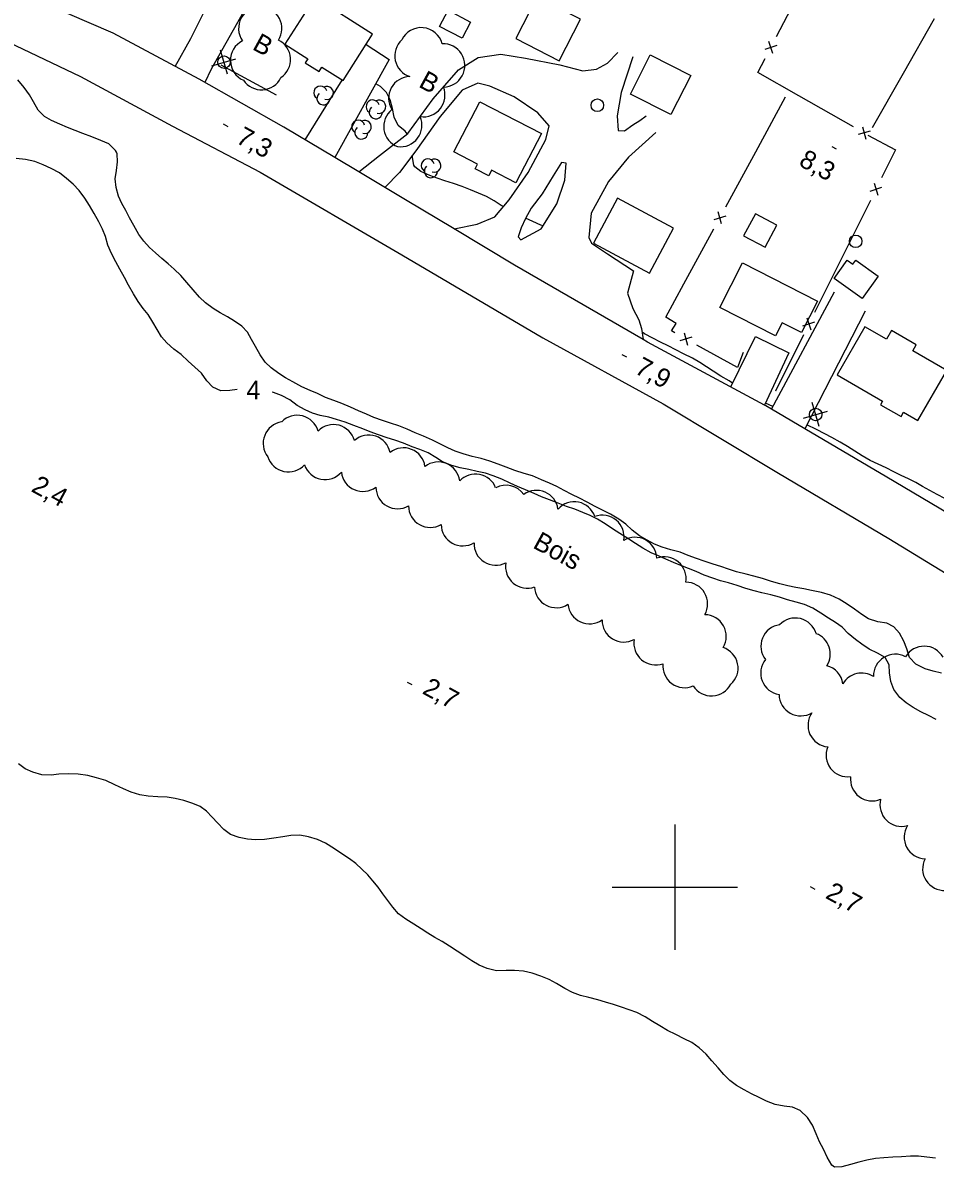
# Model space of a CAD drawing. Extents: x 219136 to 222520, y 5421589 to 5424530.
# Drawn here: x 220895.9 to 221041.6, y 5422955.3 to 5423137.9 of the extents above; entities that cross this region are included whole.
import ezdxf

# ---------------------------------------------------------------- set-up
doc = ezdxf.new("R2010")
doc.units = 0
for name, color, linetype in [('Level 19', 7, 'Continuous'), ('Level 2', 7, 'Continuous'), ('Level 21', 7, 'Continuous'), ('Level 3', 7, 'Continuous'), ('Level 31', 7, 'Continuous'), ('Level 36', 7, 'Continuous'), ('Level 37', 7, 'Continuous'), ('Level 4', 7, 'Continuous'), ('Level 44', 7, 'Continuous'), ('Level 61', 7, 'Continuous')]:
    doc.layers.add(name, color=color, linetype=linetype)

msp = doc.modelspace()

# ---------------------------------------------------------------- linework, layer by layer
at = {"layer": 'Level 19'}
for points in [[(220929.6, 5423148.91), (220934.65, 5423145.93), (220925.97, 5423130.51), (220924.96, 5423128.39)], [(220920.26, 5423130.93), (220922.77, 5423135.39), (220925.45, 5423140.81)], [(220950.72, 5423134.47), (220954.42, 5423132.05), (220945.73, 5423116.39)], [(220949.57, 5423114.1), (220952.89, 5423116.75), (220957.38, 5423120.25), (220961.41, 5423125.76), (220965.45, 5423130.42), (220968.62, 5423132.38), (220972.22, 5423132.91), (220976.18, 5423132.29), (220981.66, 5423131.19), (220985.35, 5423130.24), (220987.53, 5423130.51), (220989.26, 5423131.46), (220990.89, 5423133.17)], [(220993.31, 5423132.5), (220991.42, 5423126.77), (220990.8, 5423123.04), (220990.94, 5423120.72), (220991.99, 5423120.68), (220993.29, 5423121.62), (220994.43, 5423122.33), (220995.41, 5423123.07)], [(220940.99, 5423119.21), (220946.93, 5423128.78)], [(220964.79, 5423105.01), (220968.48, 5423105.8), (220971.27, 5423106.92), (220973.54, 5423109.66), (220976.59, 5423114.01), (220979.41, 5423119.29), (220979.95, 5423121.46), (220978.15, 5423123.52), (220974.34, 5423126.1), (220970.46, 5423127.8), (220968.57, 5423128.28), (220966.08, 5423127.15), (220962.54, 5423122.94), (220958.65, 5423117.46), (220956.07, 5423114.04), (220953.7, 5423111.63)], [(220996.98, 5423120.4), (220992.62, 5423116.45), (220989.41, 5423112.56), (220986.68, 5423107.53), (220986.27, 5423103.66), (220986.71, 5423102.74), (220989.25, 5423101.03), (220993.39, 5423098.32), (220992.43, 5423094.78), (220993.32, 5423092.31), (220994.24, 5423090.52), (220994.71, 5423089.15), (220994.96, 5423087.38)], [(220975.45, 5423103.27), (220978.68, 5423105.04), (220981.18, 5423109), (220982.45, 5423112.79), (220982.69, 5423115.5), (220981.94, 5423115.64), (220980.59, 5423113.47), (220978.85, 5423110.64), (220977.07, 5423108.33), (220976.15, 5423106.69), (220975.47, 5423105.17), (220975.01, 5423103.76), (220975.45, 5423103.27)], [(221015.43, 5423076.25), (221025.5, 5423095)], [(221030.41, 5423091.87), (221020.74, 5423073.12)], [(221008.93, 5423079.8), (221012.87, 5423087.85), (221018.21, 5423085.23), (221014.35, 5423076.87)]]:
    msp.add_lwpolyline(points, dxfattribs=at)
at = {"layer": 'Level 2'}
for points in [[(220900.48, 5423122.34), (220899.38, 5423122.94), (220898.37, 5423123.96), (220897.61, 5423125.3), (220897.01, 5423126.4), (220896.13, 5423127.61), (220895.15, 5423128.81)], [(220957.29, 5423120.18), (220956.97, 5423120.6), (220955.86, 5423121.52), (220955.21, 5423122.84), (220954.93, 5423124.21), (220954.55, 5423125.63), (220953.97, 5423126.79), (220953.01, 5423127.72), (220952.26, 5423128.16)], [(220963.77, 5423070.06), (220962.5, 5423070.72), (220961.34, 5423071.31), (220959.87, 5423071.94), (220958.55, 5423072.49), (220957.29, 5423073.06), (220955.94, 5423073.6), (220954.62, 5423074.04), (220953.34, 5423074.43), (220951.94, 5423074.93), (220950.77, 5423075.43), (220949.52, 5423076.01), (220948.22, 5423076.58), (220946.84, 5423077.15), (220945.6, 5423077.61), (220944.23, 5423078.14), (220942.99, 5423078.73), (220941.77, 5423079.23), (220940.48, 5423079.82), (220939.03, 5423080.59), (220937.88, 5423081.25), (220936.82, 5423081.92), (220935.59, 5423082.85), (220934.63, 5423083.77), (220933.79, 5423084.93), (220933.06, 5423086.24), (220932.45, 5423087.36), (220931.78, 5423088.54), (220930.87, 5423089.51), (220929.73, 5423090.31), (220928.59, 5423091.01), (220927.41, 5423091.63), (220926.3, 5423092.33), (220925.1, 5423093.23), (220924.14, 5423094.13), (220923.11, 5423095.31), (220922.11, 5423096.47), (220921.13, 5423097.59), (220920.08, 5423098.58), (220919.15, 5423099.43), (220918.1, 5423100.32), (220917.11, 5423101.18), (220916.17, 5423102.03), (220915.23, 5423103.06), (220914.43, 5423104.15), (220913.66, 5423105.55), (220912.96, 5423106.81), (220912.35, 5423107.93), (220911.74, 5423109.06), (220911.21, 5423110.24), (220910.85, 5423111.64), (220910.67, 5423113), (220910.86, 5423114.32), (220911.03, 5423115.71), (220910.97, 5423117), (220910.89, 5423117.26), (220910.73, 5423117.51), (220909.65, 5423118.59), (220908.36, 5423119.15), (220906.94, 5423119.7), (220905.5, 5423120.26), (220904.26, 5423120.72), (220903.04, 5423121.2), (220901.84, 5423121.74), (220900.48, 5423122.34)], [(220917.35, 5423088.94), (220916.68, 5423090.15), (220915.95, 5423091.36), (220915.16, 5423092.33), (220914.34, 5423093.42), (220913.57, 5423094.65), (220912.82, 5423096.02), (220912.13, 5423097.29), (220911.43, 5423098.57), (220910.79, 5423099.77), (220910.07, 5423101.12), (220909.52, 5423102.45), (220909.11, 5423103.78), (220908.65, 5423104.96), (220908.05, 5423106.14), (220907.33, 5423107.46), (220906.57, 5423108.74), (220905.84, 5423109.92), (220904.93, 5423111.15), (220903.95, 5423112.15), (220902.9, 5423113.06), (220901.78, 5423113.94), (220900.47, 5423114.65), (220899.17, 5423115.26), (220897.82, 5423115.79), (220896.35, 5423116.11), (220894.88, 5423116.24)], [(220972.65, 5423108.59), (220972.3, 5423108.78), (220971.15, 5423109.48), (220969.96, 5423110.18), (220968.65, 5423110.74), (220967.38, 5423111.26), (220966.06, 5423111.8), (220964.66, 5423112.27), (220963.29, 5423112.69), (220962.09, 5423113.11), (220960.88, 5423113.55), (220959.44, 5423114.17), (220958.48, 5423114.9), (220958.33, 5423115.17), (220958.1, 5423116.72)], [(220978.98, 5423105.52), (220978.61, 5423105.64), (220977.32, 5423106.19), (220976.18, 5423106.75)], [(220930.14, 5423079.37), (220928.99, 5423079.25), (220927.54, 5423079.19), (220926.25, 5423079.77), (220925.31, 5423080.77), (220924.46, 5423081.98), (220923.39, 5423082.93), (220922.32, 5423083.91), (220921.18, 5423084.95), (220920.03, 5423085.83), (220918.91, 5423086.85), (220918.05, 5423087.8), (220917.35, 5423088.94)], [(221005.07, 5423083.03), (221004.02, 5423083.71), (221002.83, 5423084.38), (221001.4, 5423085.07), (221000.15, 5423085.71), (220998.94, 5423086.38), (220997.73, 5423086.97), (220996.49, 5423087.57), (220995.18, 5423088.28), (220994.8, 5423088.53)], [(221009.23, 5423080.42), (221008.69, 5423080.75), (221007.38, 5423081.52), (221006.14, 5423082.33), (221005.07, 5423083.03)], [(220997.38, 5423052.83), (220996.21, 5423053.34), (220994.89, 5423054.07), (220993.74, 5423054.81), (220992.49, 5423055.6), (220991.22, 5423056.43), (220990.06, 5423057.17), (220988.88, 5423057.94), (220987.67, 5423058.69), (220986.49, 5423059.28), (220985.3, 5423059.78), (220984.05, 5423060.27), (220982.72, 5423060.74), (220981.38, 5423061.26), (220979.99, 5423061.78), (220978.74, 5423062.27), (220977.53, 5423062.81), (220976.15, 5423063.37), (220974.89, 5423063.9), (220973.73, 5423064.47), (220972.4, 5423065.07), (220971.02, 5423065.63), (220969.79, 5423066.03), (220968.47, 5423066.32), (220967.11, 5423066.62), (220965.76, 5423066.9), (220964.39, 5423067.25), (220962.93, 5423067.87), (220961.85, 5423068.55), (220960.62, 5423069.29), (220959.32, 5423069.82), (220958.07, 5423070.26), (220956.72, 5423070.82), (220955.31, 5423071.32), (220954.11, 5423071.67), (220952.7, 5423072.15), (220951.4, 5423072.62), (220950.19, 5423073.1), (220948.78, 5423073.63), (220947.38, 5423074.16), (220945.98, 5423074.62), (220944.75, 5423074.95), (220943.39, 5423075.26), (220942.16, 5423075.63), (220941.01, 5423076.15), (220939.72, 5423076.86), (220938.53, 5423077.72), (220937.2, 5423078.45), (220935.93, 5423078.91), (220935.71, 5423078.95)], [(221015.65, 5423076.66), (221014.51, 5423077.21)], [(221047.57, 5423059.42), (221046.91, 5423059.79), (221045.72, 5423060.56), (221044.38, 5423061.34), (221043.13, 5423061.98), (221041.91, 5423062.61), (221040.7, 5423063.29), (221039.57, 5423063.92), (221038.47, 5423064.56), (221037.34, 5423065.13), (221036.16, 5423065.66), (221034.98, 5423066.25), (221033.74, 5423066.87), (221032.46, 5423067.46), (221031.22, 5423068.06), (221029.94, 5423068.8), (221028.76, 5423069.54), (221027.58, 5423070.28), (221026.39, 5423071.01), (221025.1, 5423071.71), (221023.95, 5423072.32), (221022.62, 5423073.01), (221021.08, 5423073.77)], [(221042.59, 5423034.14), (221041.26, 5423034.42), (221039.98, 5423034.82), (221038.46, 5423035.57), (221037.47, 5423036.65), (221037.04, 5423038.03), (221036.59, 5423039.23), (221035.88, 5423040.51), (221034.96, 5423041.5), (221033.84, 5423042.09), (221032.4, 5423042.29), (221030.91, 5423042.77), (221029.84, 5423043.48), (221028.7, 5423044.34), (221027.53, 5423045.13), (221026.27, 5423045.92), (221024.87, 5423046.57), (221023.42, 5423046.98), (221021.83, 5423047.31), (221020.58, 5423047.59), (221019.32, 5423047.77), (221018.03, 5423048.04), (221016.79, 5423048.37), (221015.45, 5423048.73), (221014.01, 5423049.23), (221012.65, 5423049.62), (221011.42, 5423049.9), (221009.88, 5423050.31), (221008.58, 5423050.71), (221007.38, 5423051.13), (221006.11, 5423051.53), (221004.68, 5423052), (221003.45, 5423052.42), (221002.15, 5423052.92), (221000.88, 5423053.44), (220999.38, 5423053.79), (220998.01, 5423054.21), (220996.78, 5423054.73), (220995.58, 5423055.34), (220994.38, 5423056.06), (220993.2, 5423056.92), (220992.18, 5423057.89), (220991.08, 5423058.7), (220989.73, 5423059.48), (220988.56, 5423060.07), (220987.27, 5423060.72), (220986.01, 5423061.4), (220984.77, 5423062.05), (220983.56, 5423062.65), (220982.36, 5423063.25), (220981.17, 5423063.9), (220979.98, 5423064.42), (220978.7, 5423064.96), (220977.28, 5423065.59), (220975.95, 5423066), (220974.49, 5423066.44), (220973.07, 5423067.02), (220971.83, 5423067.49), (220970.48, 5423067.98), (220969.08, 5423068.39), (220967.65, 5423068.68), (220966.23, 5423069.12), (220964.96, 5423069.56), (220963.77, 5423070.06)], [(221041.75, 5423026.71), (221040.51, 5423027.36), (221039.3, 5423027.97), (221038.06, 5423028.65), (221036.92, 5423029.38), (221035.91, 5423030.25), (221034.98, 5423031.5), (221034.52, 5423032.77), (221034.29, 5423034.19), (221034.24, 5423035.46), (221033.58, 5423036.63), (221032.39, 5423037.33), (221031.06, 5423037.98), (221029.84, 5423038.73), (221028.85, 5423039.49), (221027.68, 5423040.45), (221026.73, 5423041.45), (221025.67, 5423042.19), (221024.54, 5423042.89), (221023.33, 5423043.71), (221022.03, 5423044.5), (221020.71, 5423045.07), (221019.39, 5423045.46), (221018.01, 5423045.81), (221016.73, 5423046.24), (221015.36, 5423046.61), (221013.91, 5423046.95), (221012.68, 5423047.25), (221011.36, 5423047.62), (221009.95, 5423048.12), (221008.59, 5423048.54), (221007.32, 5423048.88), (221006.06, 5423049.26), (221004.69, 5423049.77), (221003.4, 5423050.33), (221002.2, 5423050.82), (221000.96, 5423051.29), (220999.78, 5423051.76), (220998.58, 5423052.3), (220997.38, 5423052.83)]]:
    msp.add_lwpolyline(points, dxfattribs=at)
at = {"layer": 'Level 21'}
for points in [[(220870.08, 5423145.01), (220887.78, 5423137.56), (220905.12, 5423129.34), (220919.83, 5423121.43), (220933.81, 5423114.05), (220956.41, 5423100.89), (220978.92, 5423087.62), (220998.14, 5423077.12), (221016.54, 5423066.03), (221034.15, 5423055.63), (221053.45, 5423043.85), (221075.32, 5423030.79), (221097.85, 5423018.46), (221123.32, 5423005.79), (221147.81, 5422994.15), (221173.51, 5422982.42), (221197.19, 5422971.44)], [(221053.45, 5423053.81), (221033.86, 5423065.39), (221020.74, 5423073.12), (221015.43, 5423076.25), (221014.52, 5423076.78), (221014.35, 5423076.87), (220995.66, 5423086.97), (220994.96, 5423087.38), (220974.44, 5423099.25), (220964.79, 5423105.01), (220957.02, 5423109.65), (220949.57, 5423114.1), (220945.73, 5423116.39), (220937.58, 5423121.25), (220924.07, 5423128.89), (220910.33, 5423136.25), (220896.12, 5423142.44)]]:
    msp.add_lwpolyline(points, dxfattribs=at)
at = {"layer": 'Level 3'}
for p, q in [((220927.92, 5423121.76), (220928.63, 5423121.38)), ((221025.05, 5423118.16), (221025.76, 5423117.78)), ((220991.57, 5423085), (220992.27, 5423084.62)), ((220957.29, 5423032.68), (220958, 5423032.3)), ((221021.64, 5423000.06), (221022.35, 5422999.68))]:
    msp.add_line(p, q, dxfattribs=at)
at = {"layer": 'Level 31'}
for points in [[(220951.75, 5423136.11), (220942.54, 5423142), (220937.75, 5423134.51), (220941.41, 5423132.17), (220941.01, 5423131.54), (220943.22, 5423130.14), (220943.67, 5423130.85), (220947.05, 5423128.7)], [(220974.62, 5423135.38), (220981.57, 5423131.85), (220984.94, 5423138.49), (220977.99, 5423142.02)], [(220966.04, 5423135.43), (220962.45, 5423137.3), (220963.81, 5423139.9), (220967.4, 5423138.02)], [(220999.38, 5423123.27), (220992.94, 5423126.53), (220996.1, 5423132.78), (221002.54, 5423129.52)], [(220968.86, 5423125.32), (220978.7, 5423120.22), (220974.63, 5423112.37), (220970.76, 5423114.38), (220970.3, 5423113.5), (220968.15, 5423114.62), (220968.52, 5423115.35), (220964.72, 5423117.32)], [(220999.81, 5423105.12), (220990.88, 5423109.91), (220987.03, 5423102.74), (220995.96, 5423097.95)], [(221010.99, 5423103.91), (221014.41, 5423102.08), (221016.3, 5423105.61), (221012.88, 5423107.44)], [(221010.84, 5423099.61), (221022.79, 5423093.49), (221020.22, 5423088.47), (221017.17, 5423090.03), (221016.1, 5423087.94), (221007.19, 5423092.5)], [(221028.93, 5423100.04), (221032.47, 5423097.5), (221029.9, 5423093.92), (221025.43, 5423097.13), (221027.52, 5423100.04), (221028.45, 5423099.37)], [(221025.94, 5423081.73), (221033.19, 5423077.53), (221032.86, 5423076.96), (221036.12, 5423075.07), (221036.52, 5423075.76), (221038.81, 5423074.43), (221043.45, 5423082.42), (221038, 5423085.58), (221038.54, 5423086.52), (221034.58, 5423088.8), (221033.79, 5423087.42), (221030.33, 5423089.4)]]:
    msp.add_lwpolyline(points, close=True, dxfattribs=at)
at = {"layer": 'Level 36'}
for p, q in [((220926.12, 5423131.05), (220929.95, 5423132.18)), ((220928.6, 5423129.7), (220927.47, 5423133.53)), ((221023.05, 5423073.48), (221021.92, 5423077.31)), ((221020.57, 5423074.83), (221024.4, 5423075.96))]:
    msp.add_line(p, q, dxfattribs=at)
for centre in [(220928.04, 5423131.62), (220987.64, 5423124.75), (221028.89, 5423103.04), (221022.49, 5423075.4)]:
    msp.add_circle(centre, 1, dxfattribs=at)
at = {"layer": 'Level 37'}
for p, q in [((221016.29, 5423134.26), (221014.38, 5423133.66)), ((221015.64, 5423133.01), (221015.04, 5423134.92)), ((221029.99, 5423121.29), (221030.52, 5423119.36)), ((221031.22, 5423120.59), (221029.29, 5423120.06)), ((221031.17, 5423111.05), (221033.07, 5423111.68)), ((221031.81, 5423112.31), (221032.44, 5423110.42)), ((221008.16, 5423107.06), (221006.24, 5423106.49)), ((221007.48, 5423105.81), (221006.91, 5423107.73)), ((221020.47, 5423089.57), (221022.37, 5423090.2)), ((221021.1, 5423090.83), (221021.74, 5423088.93)), ((221001.49, 5423088.41), (221002.05, 5423086.49)), ((221002.73, 5423087.73), (221000.81, 5423087.17))]:
    msp.add_line(p, q, dxfattribs=at)
for points in [[(221016.26, 5423135.74), (221020.87, 5423144.61)], [(221041.43, 5423138.52), (221036.46, 5423129.84)], [(221019.83, 5423126.27), (221013.28, 5423130), (221014.42, 5423132.19)], [(220927.55, 5423131.19), (220936.35, 5423126.44)], [(221036.46, 5423129.84), (221031.49, 5423121.16)], [(221012.92, 5423117.32), (221017.7, 5423126.1)], [(221028.52, 5423121.32), (221019.83, 5423126.27)], [(221030.83, 5423120), (221035.24, 5423117.62), (221033.01, 5423113.15)], [(221008.15, 5423108.53), (221012.92, 5423117.32)], [(221031.23, 5423109.57), (221026.77, 5423100.62)], [(221001.47, 5423096.23), (221006.24, 5423105.01)], [(221026.77, 5423100.62), (221022.31, 5423091.67)], [(221000.02, 5423088.42), (220999.46, 5423088.73), (221000.23, 5423089.93), (220998.6, 5423090.94), (221001.47, 5423096.23)], [(221020.53, 5423088.09), (221016.07, 5423079.14)], [(221010.94, 5423085.3), (221010.01, 5423082.89), (221003.52, 5423086.48)], [(221016.07, 5423079.14), (221016.06, 5423079.13)]]:
    msp.add_lwpolyline(points, dxfattribs=at)
at = {"layer": 'Level 4'}
for points in [[(220930.48, 5423007.89), (220929.09, 5423008.38), (220928, 5423009.19), (220927.01, 5423010.23), (220926.17, 5423011.15), (220925.23, 5423012.08), (220924.22, 5423012.82), (220923.05, 5423013.34), (220921.61, 5423013.79), (220920.24, 5423014.11), (220918.97, 5423014.31), (220917.5, 5423014.38), (220915.91, 5423014.48), (220914.59, 5423014.71), (220913.21, 5423015.14), (220911.99, 5423015.64), (220910.63, 5423016.3), (220909.18, 5423016.98), (220907.67, 5423017.43), (220906.32, 5423017.77), (220904.77, 5423018.03), (220903.23, 5423018.08), (220901.69, 5423017.98), (220900.44, 5423017.85), (220898.94, 5423017.88), (220897.53, 5423018.31), (220896.32, 5423018.85), (220895.23, 5423019.64)], [(221007.84, 5422970.07), (221006.91, 5422971.14), (221005.92, 5422972.25), (221004.99, 5422973.33), (221003.92, 5422974.36), (221002.72, 5422975.16), (221001.51, 5422975.77), (221000.16, 5422976.44), (220998.85, 5422977.12), (220997.64, 5422977.82), (220996.47, 5422978.55), (220995.25, 5422979.3), (220993.92, 5422979.95), (220992.73, 5422980.41), (220991.49, 5422980.84), (220990.23, 5422981.24), (220988.96, 5422981.63), (220987.7, 5422981.97), (220986.26, 5422982.35), (220984.93, 5422982.7), (220983.67, 5422983.15), (220982.45, 5422983.79), (220981.13, 5422984.61), (220979.97, 5422985.25), (220978.64, 5422985.77), (220977.25, 5422986.25), (220975.87, 5422986.57), (220974.44, 5422986.68), (220973.11, 5422986.65), (220971.53, 5422986.64), (220970.06, 5422986.98), (220968.8, 5422987.55), (220967.62, 5422988.23), (220966.48, 5422988.97), (220965.25, 5422989.74), (220964.03, 5422990.55), (220962.86, 5422991.28), (220961.71, 5422991.93), (220960.6, 5422992.64), (220959.5, 5422993.35), (220958.34, 5422994.09), (220957.06, 5422994.85), (220955.92, 5422995.71), (220955, 5422996.8), (220954.2, 5422997.86), (220953.41, 5422998.9), (220952.65, 5422999.98), (220951.82, 5423000.97), (220950.98, 5423001.92), (220950.06, 5423002.87), (220949.09, 5423003.73), (220948.08, 5423004.5), (220946.85, 5423005.3), (220945.67, 5423006.09), (220944.27, 5423006.98), (220942.98, 5423007.57), (220941.52, 5423008.02), (220940.16, 5423008.28), (220938.73, 5423008.23), (220937.44, 5423008.02), (220936.01, 5423007.78), (220934.51, 5423007.58), (220933.09, 5423007.55), (220931.81, 5423007.66), (220930.48, 5423007.89)], [(221041.61, 5422956.75), (221040.24, 5422956.9), (221038.92, 5422957.05), (221037.64, 5422957.07), (221036.18, 5422956.96), (221034.81, 5422956.88), (221033.37, 5422956.8), (221032.02, 5422956.67), (221030.67, 5422956.41), (221029.37, 5422956.08), (221028.04, 5422955.72), (221026.67, 5422955.37), (221025.51, 5422955.3), (221025.29, 5422955.43), (221025.06, 5422955.63), (221024.33, 5422956.89), (221023.74, 5422958.16), (221023.1, 5422959.36), (221022.58, 5422960.6), (221021.98, 5422962.02), (221021.19, 5422963.23), (221020.03, 5422964.33), (221018.78, 5422964.85), (221017.44, 5422965.03), (221016.03, 5422965.3), (221014.67, 5422965.81), (221013.47, 5422966.41), (221012.25, 5422966.98), (221011.08, 5422967.62), (221009.88, 5422968.34), (221008.8, 5422969.13), (221007.84, 5422970.07)]]:
    msp.add_lwpolyline(points, dxfattribs=at)
at = {"layer": 'Level 44'}
for centre, radius, start, end in [((220933.83, 5423137.02), 3.46, 87.4516, 214.9443), ((220933.82, 5423137.02), 3.46, 327.2589, 87.2589), ((220959.53, 5423133.68), 3.46, 14.8323, 154.2098), ((220932.52, 5423131.92), 3.46, 116.1284, 246.4596), ((220935.2, 5423132.04), 3.46, 303.6919, 63.6919), ((220958.75, 5423132.63), 3.46, 132.4398, 252.4398), ((220963.03, 5423131.11), 3.46, 270.7312, 92.4792), ((220934.01, 5423130.68), 3.46, 213.9138, 333.9138), ((220957.78, 5423125.87), 3.46, 91.2654, 211.2654), ((220943.42, 5423126.76), 1.05, 15.4747, 238.159), ((220943.92, 5423125.85), 1.05, 130.807, 358.2641), ((220944.46, 5423126.73), 1.05, 252.6532, 118.3418), ((220959.86, 5423126.36), 3.46, 261.7986, 21.7986), ((220951.78, 5423124.54), 1.05, 15.4747, 238.159), ((220952.82, 5423124.51), 1.05, 252.6532, 118.3418), ((220952.28, 5423123.63), 1.05, 130.807, 358.2641), ((220957, 5423121.37), 3.46, 128.8917, 248.8917), ((220956.18, 5423121.58), 3.46, 262.9405, 22.9405), ((220949.47, 5423121.31), 1.05, 15.4747, 238.159), ((220949.97, 5423120.4), 1.05, 130.807, 358.2641), ((220950.51, 5423121.28), 1.05, 252.6532, 118.3418), ((220960.57, 5423115.14), 1.05, 15.4747, 238.159), ((220961.61, 5423115.11), 1.05, 252.6532, 118.3418), ((220961.07, 5423114.23), 1.05, 130.807, 358.2641), ((220939.73, 5423071.82), 3.46, 15.8517, 135.8517), ((220937.75, 5423070.8), 3.46, 98.4095, 218.4095), ((220945.53, 5423070.33), 3.46, 15.4071, 135.4071), ((220951.16, 5423068.66), 3.46, 11.4899, 131.4899), ((220956.7, 5423066.63), 3.46, 8.1858, 128.1858), ((220938.34, 5423069.69), 3.46, 197.4986, 317.4986), ((220944.17, 5423068.47), 3.46, 198.79, 318.79), ((220950.22, 5423066.58), 3.46, 186.4762, 306.4762), ((220962.24, 5423064.37), 3.46, 7.4411, 127.4412), ((220968.19, 5423062.44), 3.46, 21.5438, 136.6511), ((220955.75, 5423063.81), 3.46, 180.288, 300.288), ((220973.06, 5423060.66), 3.46, 34.9283, 118.4422), ((220977.93, 5423059.84), 3.46, 7.7777, 125.896), ((220960.96, 5423060.83), 3.46, 180.1315, 300.1315), ((220983.96, 5423058.02), 3.46, 18.6022, 138.6022), ((220988.45, 5423055.88), 3.46, 350.2619, 110.2619), ((220966.16, 5423057.9), 3.46, 181.0943, 301.0943), ((220993.69, 5423052.35), 3.46, 1.95, 121.95), ((220971.41, 5423054.8), 3.46, 177.79, 297.79), ((220976.44, 5423051.13), 3.46, 169.9867, 289.9867), ((220998.35, 5423049.22), 3.46, 350.2259, 110.2259), ((220981.08, 5423048.03), 3.46, 182.5937, 302.5937), ((221001.79, 5423045.17), 3.46, 330.46, 90.46), ((220986.39, 5423045.45), 3.46, 185.526, 305.526), ((220991.87, 5423042.54), 3.46, 178.6263, 298.6263), ((221004.76, 5423039.99), 3.46, 329.1249, 89.1249), ((221019.24, 5423039.46), 3.46, 16.2999, 136.2999), ((221017.21, 5423038.42), 3.46, 97.8657, 217.8657), ((220996.94, 5423038.89), 3.46, 169.7794, 289.7794), ((221021.37, 5423037.18), 3.46, 327.4882, 69.7511), ((221006.65, 5423034.93), 3.46, 311.7784, 71.7784), ((221035.19, 5423033.69), 3.46, 61.6144, 181.6144), ((221039.82, 5423034.97), 3.46, 29.3385, 149.3385), ((221001.56, 5423035.26), 3.46, 173.8804, 293.8804), ((221017.18, 5423034.13), 3.46, 141.194, 261.194), ((221023.41, 5423031.97), 3.46, 7.9185, 75.3215), ((221029.83, 5423030.69), 3.46, 56.7213, 149.5474), ((221005.88, 5423033.95), 3.46, 212.3956, 332.3956), ((221020.11, 5423030.77), 3.46, 181.1937, 301.1937), ((221024.73, 5423025.81), 3.46, 144.7802, 264.7802), ((221027.62, 5423021.04), 3.46, 157.4481, 277.4481), ((221031.51, 5423017.19), 3.46, 173.1599, 293.1599), ((221036.22, 5423013.13), 3.46, 165.4515, 285.4515), ((221040.08, 5423007.95), 3.46, 147.841, 267.841), ((221043.03, 5423002.91), 3.46, 152.8894, 272.8894)]:
    msp.add_arc(centre, radius, start, end, dxfattribs=at)
at = {"layer": 'Level 61'}
for points in [[(221000, 5423010), (221000, 5423000), (221000, 5422990)], [(220990, 5423000), (221000, 5423000), (221010, 5423000)]]:
    msp.add_lwpolyline(points, dxfattribs=at)

# ---------------------------------------------------------------- texts
at = {"layer": 'Level 2'}
msp.add_text('4', height=3, rotation=359.0667, dxfattribs=at).set_placement((220931.61, 5423077.85))
at = {"layer": 'Level 3'}
for s, p in [('7,3', (220929.78, 5423118.86)), ('8,3', (221019.63, 5423115.22)), ('7,9', (220993.42, 5423082.1)), ('2,4', (220897.1, 5423063.21)), ('2,7', (220959.54, 5423030.95)), ('2,7', (221023.89, 5422998.32))]:
    msp.add_text(s, height=3, rotation=331.383, dxfattribs=at).set_placement(p)
at = {"layer": 'Level 44'}
for s, p in [('B', (220932.41, 5423133.75)), ('B', (220958.95, 5423127.78)), ('Bois', (220977.18, 5423054.21))]:
    msp.add_text(s, height=3, rotation=331.3547, dxfattribs=at).set_placement(p)

doc.saveas('drawing.dxf')
